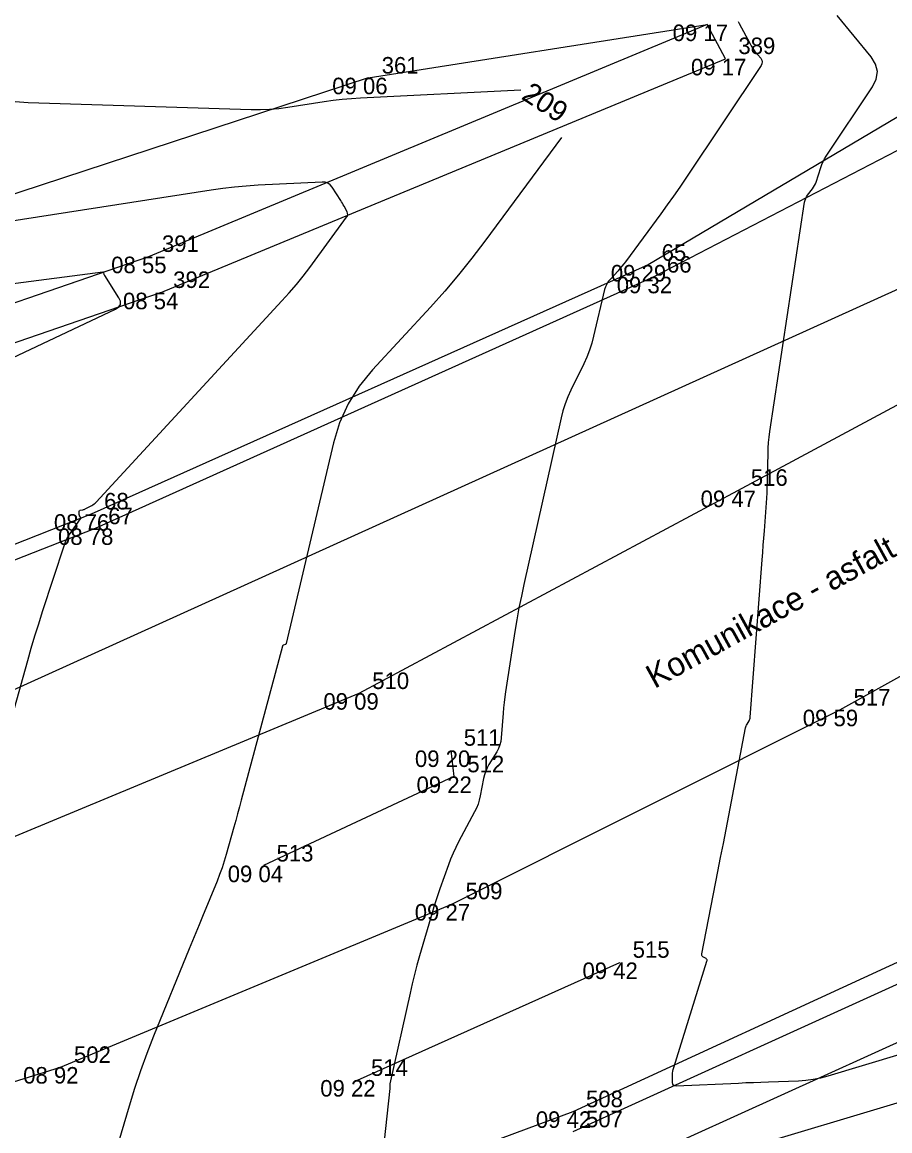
# Model space of a CAD drawing. Extents: x -711234 to -710007, y -1026313 to -1025448.
# Drawn here: x -710993.01 to -710978.32, y -1025895.88 to -1025877.11 of the extents above; entities that cross this region are included whole.
import ezdxf

# ---------------------------------------------------------------- set-up
doc = ezdxf.new("R2010")
doc.units = 0
for name, color, linetype in [('Ex_Contour Labels', 7, 'Continuous'), ('Ex_Major Contours', 7, 'Continuous'), ('Ex_Minor Contours', 7, 'Continuous'), ('Z_body', 7, 'Continuous'), ('Z_body_cisla', 7, 'Continuous'), ('Z_body_vysky_redukovane', 7, 'Continuous'), ('Z_hrany_paty', 7, 'Continuous'), ('Z_katastr_hranice', 7, 'Continuous'), ('Z_komunikace', 7, 'Continuous'), ('Z_popisy', 7, 'Continuous'), ('Z_vdz12_plna', 7, 'Continuous'), ('Z_vdz12_prerusovana', 7, 'Continuous'), ('Z_vdz25_plna', 7, 'Continuous'), ('Z_vdz_sipky', 7, 'Continuous'), ('Z_zlabek', 7, 'Continuous')]:
    doc.layers.add(name, color=color, linetype=linetype)

# ---------------------------------------------------------------- blocks, each defined once
blk = doc.blocks.new('POINT_DISPLAY')
blk.add_line((0, 0), (0, 0))

msp = doc.modelspace()

# ---------------------------------------------------------------- linework, layer by layer
at = {"layer": 'Ex_Major Contours'}
for points in [[(-710993.579, -1025878.418), (-710992.905, -1025878.471), (-710989.129, -1025878.588), (-710988.973, -1025878.589), (-710988.819, -1025878.583), (-710988.664, -1025878.57), (-710988.51, -1025878.55), (-710987.895, -1025878.454), (-710987.741, -1025878.432), (-710987.587, -1025878.415), (-710987.432, -1025878.401), (-710987.277, -1025878.391), (-710984.566, -1025878.256)], [(-710983.877, -1025879.062), (-710985.174, -1025880.819), (-710985.393, -1025881.107), (-710985.619, -1025881.389), (-710985.853, -1025881.664), (-710986.095, -1025881.934), (-710987.078, -1025882.997), (-710987.304, -1025883.274), (-710987.488, -1025883.572), (-710987.632, -1025883.892), (-710987.736, -1025884.234), (-710988.535, -1025887.629), (-710988.537, -1025887.635), (-710988.541, -1025887.641), (-710988.546, -1025887.645), (-710988.553, -1025887.648), (-710988.583, -1025887.656), (-710988.59, -1025887.659), (-710988.595, -1025887.663), (-710988.599, -1025887.668), (-710988.602, -1025887.675), (-710989.297, -1025890.281), (-710989.328, -1025890.396), (-710989.359, -1025890.511), (-710989.391, -1025890.626), (-710989.423, -1025890.741), (-710989.552, -1025891.2), (-710989.586, -1025891.315), (-710989.623, -1025891.428), (-710989.664, -1025891.54), (-710989.707, -1025891.651), (-710989.954, -1025892.253), (-710990.01, -1025892.39), (-710990.067, -1025892.527), (-710990.123, -1025892.664), (-710990.179, -1025892.801), (-710990.781, -1025894.276), (-710990.896, -1025894.568), (-710991.004, -1025894.864), (-710991.104, -1025895.162), (-710991.197, -1025895.463), (-710992.042, -1025898.32)]]:
    msp.add_lwpolyline(points, dxfattribs=at)
at = {"layer": 'Ex_Minor Contours'}
for points in [[(-710980.885, -1025877.101), (-710980.868, -1025877.131), (-710980.683, -1025877.477), (-710980.665, -1025877.51), (-710980.644, -1025877.542), (-710980.622, -1025877.574), (-710980.599, -1025877.604), (-710980.502, -1025877.722), (-710980.483, -1025877.752), (-710980.476, -1025877.782), (-710980.481, -1025877.813), (-710980.496, -1025877.845), (-710981.768, -1025879.75), (-710981.872, -1025879.903), (-710981.977, -1025880.054), (-710982.084, -1025880.205), (-710982.193, -1025880.354), (-710982.791, -1025881.165), (-710982.821, -1025881.204), (-710982.853, -1025881.243), (-710982.885, -1025881.281), (-710982.918, -1025881.318), (-710983.054, -1025881.465), (-710983.085, -1025881.503), (-710983.11, -1025881.544), (-710983.13, -1025881.589), (-710983.145, -1025881.636), (-710983.331, -1025882.427), (-710983.363, -1025882.547), (-710983.401, -1025882.665), (-710983.446, -1025882.781), (-710983.498, -1025882.894), (-710983.719, -1025883.342), (-710983.77, -1025883.455), (-710983.815, -1025883.571), (-710983.852, -1025883.689), (-710983.883, -1025883.809), (-710984.513, -1025886.631), (-710984.555, -1025886.829), (-710984.595, -1025887.027), (-710984.631, -1025887.226), (-710984.663, -1025887.426), (-710984.822, -1025888.445), (-710984.835, -1025888.535), (-710984.846, -1025888.626), (-710984.856, -1025888.716), (-710984.864, -1025888.807), (-710984.895, -1025889.224), (-710984.904, -1025889.287), (-710984.919, -1025889.347), (-710984.942, -1025889.405), (-710984.971, -1025889.461), (-710985.104, -1025889.679), (-710985.134, -1025889.735), (-710985.159, -1025889.792), (-710985.179, -1025889.852), (-710985.194, -1025889.914), (-710985.251, -1025890.211), (-710985.267, -1025890.281), (-710985.289, -1025890.349), (-710985.315, -1025890.415), (-710985.346, -1025890.479), (-710985.617, -1025890.987), (-710985.666, -1025891.082), (-710985.711, -1025891.179), (-710985.752, -1025891.278), (-710985.79, -1025891.378), (-710985.935, -1025891.782), (-710985.97, -1025891.883), (-710986.004, -1025891.984), (-710986.037, -1025892.087), (-710986.067, -1025892.189), (-710986.279, -1025892.92), (-710986.323, -1025893.076), (-710986.365, -1025893.233), (-710986.404, -1025893.391), (-710986.44, -1025893.549), (-710986.78, -1025895.087), (-710986.781, -1025895.093), (-710986.782, -1025895.1), (-710986.782, -1025895.106), (-710986.783, -1025895.112), (-710986.783, -1025895.138), (-710986.783, -1025895.144), (-710986.783, -1025895.15), (-710986.783, -1025895.157), (-710986.784, -1025895.163), (-710986.981, -1025896.986)], [(-710976.928, -1025894.223), (-710979.367, -1025894.954), (-710979.489, -1025894.987), (-710979.613, -1025895.011), (-710979.738, -1025895.028), (-710979.864, -1025895.037), (-710980.372, -1025895.055), (-710980.499, -1025895.06), (-710980.626, -1025895.065), (-710980.753, -1025895.07), (-710980.88, -1025895.076), (-710981.931, -1025895.122), (-710981.959, -1025895.119), (-710981.979, -1025895.108), (-710981.991, -1025895.089), (-710981.995, -1025895.061), (-710981.995, -1025894.934), (-710981.994, -1025894.902), (-710981.99, -1025894.871), (-710981.984, -1025894.84), (-710981.976, -1025894.809), (-710981.412, -1025893.009), (-710981.409, -1025892.995), (-710981.411, -1025892.983), (-710981.418, -1025892.973), (-710981.428, -1025892.964), (-710981.48, -1025892.932), (-710981.491, -1025892.923), (-710981.498, -1025892.913), (-710981.501, -1025892.9), (-710981.5, -1025892.886), (-710981.227, -1025891.491), (-710981.181, -1025891.253), (-710981.135, -1025891.016), (-710981.089, -1025890.778), (-710981.043, -1025890.541), (-710980.757, -1025889.058), (-710980.753, -1025889.042), (-710980.748, -1025889.026), (-710980.741, -1025889.011), (-710980.733, -1025888.996), (-710980.698, -1025888.938), (-710980.69, -1025888.923), (-710980.685, -1025888.908), (-710980.68, -1025888.892), (-710980.678, -1025888.876), (-710980.476, -1025886.214), (-710980.467, -1025886.091), (-710980.458, -1025885.967), (-710980.449, -1025885.844), (-710980.44, -1025885.721), (-710980.401, -1025885.17), (-710980.395, -1025885.076), (-710980.391, -1025884.982), (-710980.387, -1025884.888), (-710980.385, -1025884.793), (-710980.377, -1025884.416), (-710980.374, -1025884.322), (-710980.368, -1025884.228), (-710980.358, -1025884.134), (-710980.346, -1025884.041), (-710979.758, -1025880.157), (-710979.752, -1025880.125), (-710979.741, -1025880.094), (-710979.726, -1025880.065), (-710979.708, -1025880.038), (-710979.626, -1025879.933), (-710979.607, -1025879.906), (-710979.59, -1025879.877), (-710979.576, -1025879.848), (-710979.565, -1025879.816), (-710979.486, -1025879.571), (-710979.468, -1025879.52), (-710979.447, -1025879.471), (-710979.422, -1025879.424), (-710979.393, -1025879.378), (-710978.609, -1025878.203), (-710978.545, -1025878.073), (-710978.527, -1025877.946), (-710978.557, -1025877.82), (-710978.633, -1025877.697), (-710979.206, -1025876.997)], [(-710993.901, -1025891.43), (-710992.913, -1025887.918), (-710992.854, -1025887.71), (-710992.792, -1025887.502), (-710992.727, -1025887.295), (-710992.661, -1025887.089), (-710992.29, -1025885.956), (-710992.271, -1025885.906), (-710992.249, -1025885.858), (-710992.224, -1025885.811), (-710992.195, -1025885.767), (-710992.018, -1025885.52), (-710992.014, -1025885.513), (-710992.013, -1025885.506), (-710992.014, -1025885.499), (-710992.017, -1025885.492), (-710992.035, -1025885.465), (-710992.039, -1025885.458), (-710992.041, -1025885.45), (-710992.043, -1025885.443), (-710992.043, -1025885.435), (-710992.042, -1025885.395), (-710992.04, -1025885.387), (-710992.036, -1025885.38), (-710992.031, -1025885.376), (-710992.023, -1025885.373), (-710991.978, -1025885.364), (-710991.968, -1025885.362), (-710991.958, -1025885.359), (-710991.948, -1025885.355), (-710991.938, -1025885.35), (-710991.829, -1025885.292), (-710991.809, -1025885.28), (-710991.789, -1025885.266), (-710991.771, -1025885.251), (-710991.754, -1025885.234), (-710988.608, -1025881.83), (-710988.484, -1025881.692), (-710988.365, -1025881.552), (-710988.25, -1025881.408), (-710988.138, -1025881.261), (-710987.513, -1025880.414), (-710987.5, -1025880.392), (-710987.495, -1025880.369), (-710987.497, -1025880.346), (-710987.506, -1025880.322), (-710987.557, -1025880.225), (-710987.571, -1025880.201), (-710987.584, -1025880.177), (-710987.598, -1025880.154), (-710987.613, -1025880.131), (-710987.76, -1025879.903), (-710987.792, -1025879.864), (-710987.831, -1025879.836), (-710987.876, -1025879.821), (-710987.927, -1025879.818), (-710989.013, -1025879.872), (-710989.212, -1025879.884), (-710989.41, -1025879.902), (-710989.608, -1025879.925), (-710989.805, -1025879.953), (-710995.44, -1025880.829)], [(-710994.826, -1025883.574), (-710991.427, -1025881.969), (-710991.372, -1025881.932), (-710991.345, -1025881.888), (-710991.344, -1025881.836), (-710991.371, -1025881.776), (-710991.61, -1025881.401), (-710991.613, -1025881.396), (-710991.616, -1025881.391), (-710991.618, -1025881.385), (-710991.62, -1025881.379), (-710991.627, -1025881.355), (-710991.629, -1025881.35), (-710991.632, -1025881.346), (-710991.637, -1025881.345), (-710991.642, -1025881.345), (-710998.058, -1025882.178)], [(-710982.278, -1025896.632), (-710976.626, -1025894.936), (-710975.977, -1025894.735), (-710975.332, -1025894.522), (-710974.69, -1025894.298), (-710974.053, -1025894.062), (-710970.328, -1025892.644), (-710970.284, -1025892.628), (-710970.24, -1025892.613), (-710970.196, -1025892.598), (-710970.151, -1025892.584), (-710969.972, -1025892.529), (-710969.927, -1025892.515), (-710969.883, -1025892.501), (-710969.839, -1025892.485), (-710969.795, -1025892.469), (-710961.655, -1025889.338)]]:
    msp.add_lwpolyline(points, dxfattribs=at)
at = {"layer": 'Z_hrany_paty'}
for p, q in [((-710987.15, -1025878.05), (-710981.41, -1025877.15)), ((-710987.15, -1025878.05), (-710997.99, -1025881.61)), ((-710983.39, -1025896.74), (-710976.46, -1025893.6))]:
    msp.add_line(p, q, dxfattribs=at)
at = {"layer": 'Z_katastr_hranice'}
msp.add_lwpolyline([(-710972.26, -1025878.16), (-710977.8, -1025881.46), (-710995.88, -1025889.65), (-710999.94, -1025888.16), (-711024.11, -1025879.36), (-711040.72, -1025866.26), (-711042.93, -1025856.02), (-711044.76, -1025843.64), (-711031.03, -1025820.33), (-711020.22, -1025809.15), (-711017.96, -1025806.65)], dxfattribs=at)
at = {"layer": 'Z_komunikace'}
for p, q in [((-710977.06, -1025878.05), (-710982.41, -1025881.22)), ((-710982.41, -1025881.22), (-710991.84, -1025885.44)), ((-710991.84, -1025885.44), (-710999.07, -1025888.29)), ((-710983.68, -1025895.89), (-710976.94, -1025892.83))]:
    msp.add_line(p, q, dxfattribs=at)
at = {"layer": 'Z_vdz12_plna'}
for p, q in [((-710980.89, -1025885.04), (-710970.8, -1025879.61)), ((-710979.16, -1025888.75), (-710968.77, -1025882.98)), ((-710987.3, -1025888.47), (-710980.89, -1025885.04)), ((-710995.19, -1025891.75), (-710987.3, -1025888.47)), ((-710985.73, -1025892.04), (-710979.16, -1025888.75)), ((-710992.36, -1025894.8), (-710985.73, -1025892.04))]:
    msp.add_line(p, q, dxfattribs=at)
at = {"layer": 'Z_vdz12_prerusovana'}
msp.add_line((-710993.85, -1025895.27), (-710992.36, -1025894.8), dxfattribs=at)
at = {"layer": 'Z_vdz25_plna'}
for p, q in [((-710976.76, -1025878.54), (-710982.31, -1025881.42)), ((-710982.31, -1025881.42), (-710991.77, -1025885.68)), ((-710991.77, -1025885.68), (-710999.12, -1025888.57)), ((-710983.68, -1025895.55), (-710977.18, -1025892.56)), ((-710992.92, -1025898.99), (-710983.68, -1025895.55))]:
    msp.add_line(p, q, dxfattribs=at)
at = {"layer": 'Z_vdz_sipky'}
for p, q in [((-710985.75, -1025889.44), (-710985.7, -1025889.88)), ((-710985.7, -1025889.88), (-710988.92, -1025891.39)), ((-710987.33, -1025895.02), (-710982.89, -1025893.03))]:
    msp.add_line(p, q, dxfattribs=at)
at = {"layer": 'Z_zlabek'}
for p, q in [((-710981.41, -1025877.15), (-710990.87, -1025881.08)), ((-710981.1, -1025877.73), (-710981.41, -1025877.15)), ((-710990.67, -1025881.69), (-710981.1, -1025877.73)), ((-710990.87, -1025881.08), (-711000.75, -1025884.5)), ((-710990.67, -1025881.69), (-711000.43, -1025885.06))]:
    msp.add_line(p, q, dxfattribs=at)

# ---------------------------------------------------------------- block references
at = {"layer": 'Z_body'}
for p in [(-710981.41, -1025877.15), (-710981.1, -1025877.73), (-710987.15, -1025878.05), (-710990.87, -1025881.08), (-710982.41, -1025881.22), (-710982.31, -1025881.42), (-710990.67, -1025881.69), (-710980.89, -1025885.04), (-710991.84, -1025885.44), (-710991.77, -1025885.68), (-710987.3, -1025888.47), (-710979.16, -1025888.75), (-710985.75, -1025889.44), (-710985.7, -1025889.88), (-710988.92, -1025891.39), (-710985.73, -1025892.04), (-710982.89, -1025893.03), (-710992.36, -1025894.8), (-710987.33, -1025895.02), (-710983.68, -1025895.55)]:
    msp.add_blockref('POINT_DISPLAY', p, dxfattribs=at)

# ---------------------------------------------------------------- texts
at = {"layer": 'Ex_Contour Labels'}
msp.add_text('209', height=0.35, rotation=326.7929, dxfattribs=at).set_placement((-710984.572, -1025878.398))
at = {"layer": 'Z_body_cisla'}
for s, p in [('389', (-710980.88, -1025877.65)), ('361', (-710986.92, -1025877.98)), ('391', (-710990.64, -1025881)), ('65', (-710982.18, -1025881.15)), ('66', (-710982.09, -1025881.35)), ('392', (-710990.45, -1025881.61)), ('516', (-710980.67, -1025884.96)), ('68', (-710991.62, -1025885.36)), ('67', (-710991.55, -1025885.61)), ('510', (-710987.08, -1025888.4)), ('517', (-710978.93, -1025888.68)), ('511', (-710985.53, -1025889.36)), ('512', (-710985.47, -1025889.81)), ('513', (-710988.7, -1025891.32)), ('509', (-710985.5, -1025891.96)), ('515', (-710982.67, -1025892.95)), ('502', (-710992.13, -1025894.73)), ('514', (-710987.1, -1025894.95)), ('508', (-710983.46, -1025895.48)), ('507', (-710983.46, -1025895.82))]:
    msp.add_text(s, height=0.28, dxfattribs=at).set_placement(p)
at = {"layer": 'Z_body_vysky_redukovane'}
for s, p in [('09 17', (-710981.993, -1025877.43)), ('09 17', (-710981.683, -1025878.01)), ('09 06', (-710987.757, -1025878.33)), ('08 55', (-710991.5, -1025881.36)), ('09 29', (-710983.04, -1025881.5)), ('09 32', (-710982.94, -1025881.7)), ('08 54', (-710991.3, -1025881.97)), ('09 47', (-710981.52, -1025885.32)), ('08 76', (-710992.47, -1025885.72)), ('08 78', (-710992.4, -1025885.96)), ('09 09', (-710987.907, -1025888.75)), ('09 59', (-710979.79, -1025889.03)), ('09 20', (-710986.357, -1025889.72)), ('09 22', (-710986.33, -1025890.16)), ('09 04', (-710989.527, -1025891.67)), ('09 27', (-710986.36, -1025892.32)), ('09 42', (-710983.52, -1025893.31)), ('08 92', (-710992.99, -1025895.08)), ('09 22', (-710987.96, -1025895.3)), ('09 42', (-710984.31, -1025895.83))]:
    msp.add_text(s, height=0.28, dxfattribs=at).set_placement(p)
at = {"layer": 'Z_popisy'}
msp.add_text('Komunikace - asfalt', height=0.4, rotation=28.8, dxfattribs=at).set_placement((-710982.3, -1025888.4))

doc.saveas('drawing.dxf')
